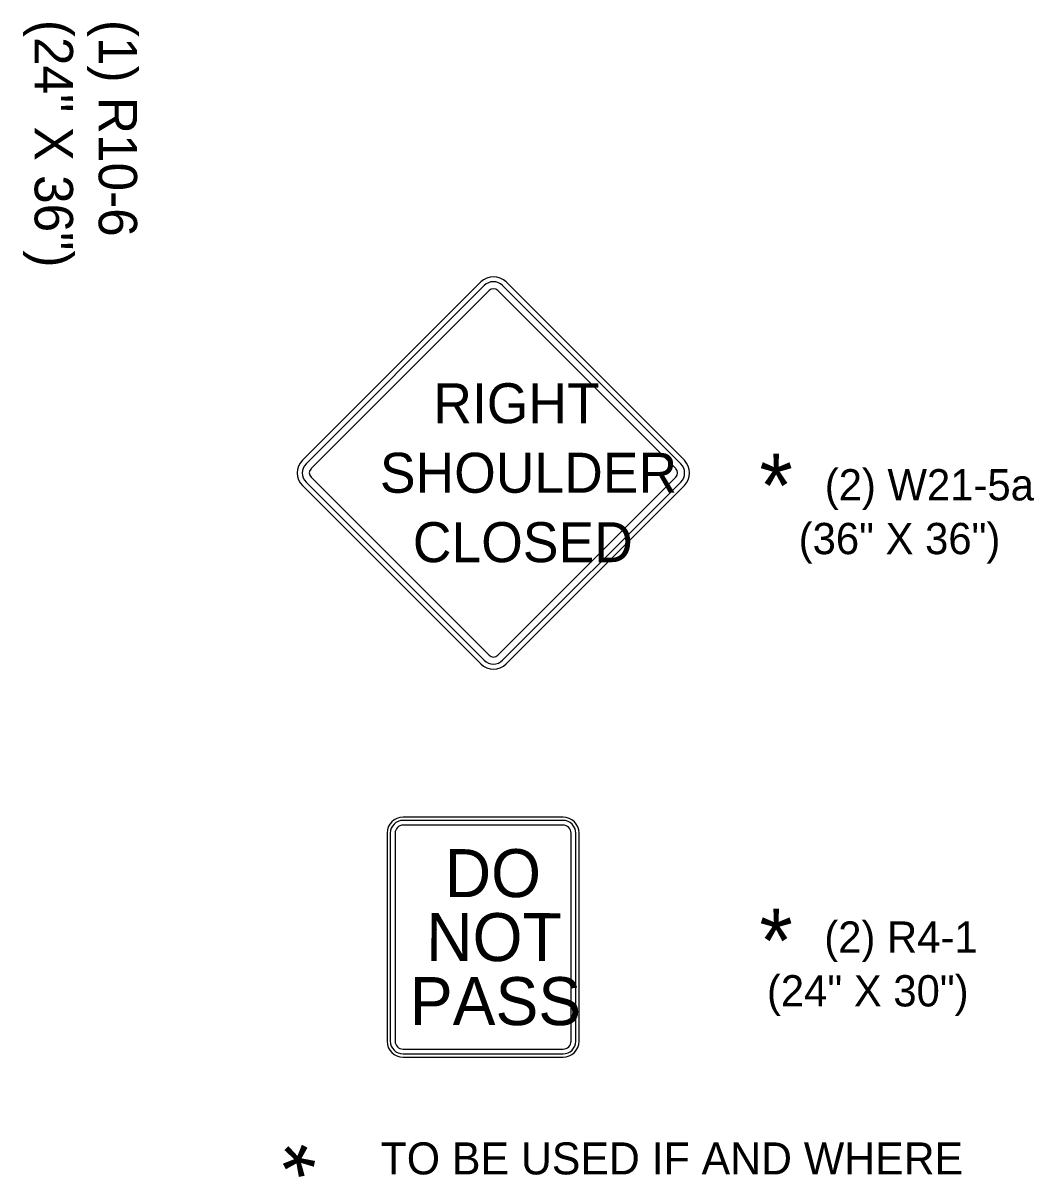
# Model space of a CAD drawing. Extents: x 1930579 to 1939784, y 596179 to 597522.
# Drawn here: x 1938130.5 to 1938288.4, y 596662.4 to 596842.7 of the extents above; entities that cross this region are included whole.
import ezdxf

# ---------------------------------------------------------------- set-up
doc = ezdxf.new("R2010")
doc.units = 0
for name, color, linetype in [('P_TC_Signs_Permanent', 7, 'Continuous'), ('P_TC_Signs_Temporary', 7, 'Continuous'), ('R_Annotation', 7, 'Continuous'), ('R_Border', 7, 'Continuous')]:
    doc.layers.add(name, color=color, linetype=linetype)

msp = doc.modelspace()

# ---------------------------------------------------------------- linework, layer by layer
at = {"layer": 'P_TC_Signs_Permanent'}
for p, q in [((1938214.85, 596718.62), (1938189.85, 596718.62)), ((1938214.85, 596718.12), (1938189.85, 596718.12)), ((1938187.35, 596716.12), (1938187.35, 596683.62)), ((1938187.85, 596716.12), (1938187.85, 596683.62)), ((1938188.6, 596716.12), (1938188.6, 596683.62)), ((1938214.85, 596717.37), (1938189.85, 596717.37)), ((1938216.1, 596683.62), (1938216.1, 596716.12)), ((1938216.85, 596683.62), (1938216.85, 596716.12)), ((1938217.35, 596683.62), (1938217.35, 596716.12)), ((1938189.85, 596682.37), (1938214.85, 596682.37)), ((1938189.85, 596681.62), (1938214.85, 596681.62)), ((1938189.85, 596681.12), (1938214.85, 596681.12))]:
    msp.add_line(p, q, dxfattribs=at)
for centre, radius, start, end in [((1938189.85, 596716.12), 2.5, 90, 180), ((1938189.85, 596716.12), 2, 90, 180), ((1938214.85, 596716.12), 2.5, 360, 90), ((1938214.85, 596716.12), 2, 360, 90), ((1938189.85, 596716.12), 1.25, 90, 180), ((1938214.85, 596716.12), 1.25, 360, 90), ((1938189.85, 596683.62), 2.5, 180, 270), ((1938189.85, 596683.62), 2, 180, 270), ((1938189.85, 596683.62), 1.25, 180, 270), ((1938214.85, 596683.62), 2.5, 270, 360), ((1938214.85, 596683.62), 2, 270, 360), ((1938214.85, 596683.62), 1.25, 270, 360)]:
    msp.add_arc(centre, radius, start, end, dxfattribs=at)
at = {"layer": 'P_TC_Signs_Temporary'}
for p, q in [((1938174.15, 596774.41), (1938201.99, 596802.26)), ((1938205.96, 596802.26), (1938233.81, 596774.41)), ((1938174.7, 596773.86), (1938202.54, 596801.7)), ((1938175.47, 596773.09), (1938203.31, 596800.93)), ((1938204.64, 596800.93), (1938232.48, 596773.09)), ((1938205.41, 596801.7), (1938233.25, 596773.86)), ((1938203.31, 596743.92), (1938175.47, 596771.76)), ((1938232.48, 596771.76), (1938204.64, 596743.92)), ((1938201.99, 596742.59), (1938174.15, 596770.44)), ((1938202.54, 596743.15), (1938174.7, 596770.99)), ((1938233.25, 596770.99), (1938205.41, 596743.15)), ((1938233.81, 596770.44), (1938205.96, 596742.59))]:
    msp.add_line(p, q, dxfattribs=at)
for centre, radius, start, end in [((1938203.98, 596800.27), 2.81, 45, 135), ((1938203.98, 596800.27), 2.03, 45, 135), ((1938203.98, 596800.27), 0.937, 45, 135), ((1938176.13, 596772.42), 2.81, 135, 225), ((1938176.13, 596772.42), 2.03, 135, 225), ((1938231.82, 596772.42), 2.03, 315, 45), ((1938231.82, 596772.42), 2.81, 315, 45), ((1938176.13, 596772.42), 0.937, 135, 225), ((1938231.82, 596772.42), 0.937, 315, 45), ((1938203.98, 596744.58), 2.03, 225, 315), ((1938203.98, 596744.58), 0.937, 225, 315), ((1938203.98, 596744.58), 2.81, 225, 315)]:
    msp.add_arc(centre, radius, start, end, dxfattribs=at)

# ---------------------------------------------------------------- texts
at = {"layer": 'P_TC_Signs_Permanent'}
for s, rotation, p in [('DO', 360, (1938196.37, 596706.12)), ('NOT', 359.9596, (1938193.47, 596696.13)), ('PASS', 360, (1938190.92, 596686.12))]:
    msp.add_text(s, height=7.5, rotation=rotation, dxfattribs=at).set_placement(p)
at = {"layer": 'P_TC_Signs_Temporary'}
for s, p in [('RIGHT', (1938194.58, 596780.18)), ('SHOULDER', (1938186.23, 596769.32)), ('CLOSED', (1938191.38, 596758.47))]:
    msp.add_text(s, height=6.25, rotation=360, dxfattribs=at).set_placement(p)
at = {"layer": 'R_Annotation'}
for s, height, rotation, p in [('(24" X 36")', 5.9996, 270, (1938132.28, 596843.22)), ('(1) R10-6', 6, 270, (1938142.29, 596843.22)), ('(2) W21-5a', 4.886, 360, (1938255.75, 596768.12)), ('(36" X 36")', 4.886, 360, (1938251.67, 596759.72)), ('(2) R4-1', 4.886, 360, (1938255.67, 596697.44)), ('(24" X 30")', 4.886, 360, (1938246.71, 596689.04)), ('*', 10, 45, (1938176.83, 596657.99)), ('TO BE USED IF AND WHERE', 5, 360, (1938186.35, 596662.79))]:
    msp.add_text(s, height=height, rotation=rotation, dxfattribs=at).set_placement(p)
at = {"layer": 'R_Border'}
for p in [(1938245.54, 596765.45), (1938245.54, 596694.33)]:
    msp.add_text('*', height=10, rotation=360, dxfattribs=at).set_placement(p)

doc.saveas('drawing.dxf')
